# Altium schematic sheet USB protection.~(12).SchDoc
size A3; SheetNumber: 7; SheetTotal: 7
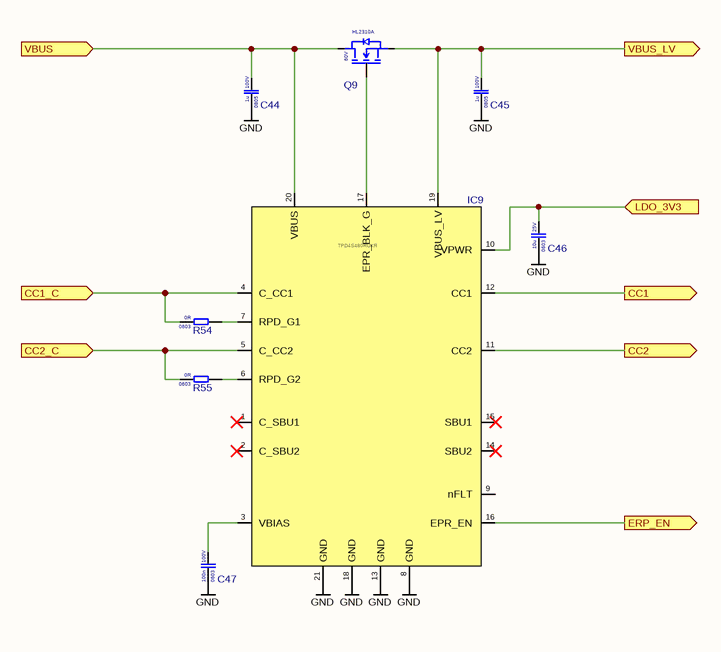
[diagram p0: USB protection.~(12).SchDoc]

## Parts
C44  Voltage Rating: 100V  Case Code (Imperial): 0805  Capacitance: 1u  [Cap_0805]  (hidden comment: CC0805KKX7R0BB105)
C45  Voltage Rating: 100V  Case Code (Imperial): 0805  Capacitance: 1u  [Cap_0805]  (hidden comment: CC0805KKX7R0BB105)
C46  Voltage Rating: 25V  Case Code (Imperial): 0603  Capacitance: 10u  [CAP 0603]  (hidden comment: CL10A106MA8NRNC)
C47  Voltage Rating: 100V  Case Code (Imperial): 0603  Capacitance: 100n  [CAP 0603]  (hidden comment: CC0603KRX7R0BB104)
IC9  TPD4S480RUKR  [WQFN (20)]
Q9  Voltage: 60V  [SOT-23 GSD]  (hidden comment: HL2310A)
R54  Resistance: 0R  Case Code (Imperial): 0603  [RES_0603]  (hidden comment: 0603WAF0000T5E)
R55  Resistance: 0R  Case Code (Imperial): 0603  [RES_0603]  (hidden comment: 0603WAF0000T5E)

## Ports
CC1 (out, see Arhitecture[3B], USB PD[3C]), CC1_C (in, see Arhitecture[2B]), CC2 (out, see Arhitecture[3B], USB PD[3C]), CC2_C (in, see Arhitecture[2B]), ERP_EN (out, see Arhitecture[3B], USB PD[5B]), LDO_3V3 (in, see Arhitecture[3B], USB PD[3C]), VBUS (in, see Arhitecture[2B], Power path switch[3B]), VBUS_LV (out, see Arhitecture[3B], USB PD[3B])

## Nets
GND: C44.1 C45.1 C46.1 C47.1 IC9.8(GND) IC9.13(GND) IC9.18(GND) IC9.21(GND)
CC1: IC9.12(CC1) ; port CC1
CC1_C: IC9.4(C_CC1) R54.1 ; port CC1_C
CC2: IC9.11(CC2) ; port CC2
CC2_C: IC9.5(C_CC2) R55.1 ; port CC2_C
ERP_EN: IC9.16(EPR_EN) ; port ERP_EN
LDO_3V3: C46.2 IC9.10(VPWR) ; port LDO_3V3
VBUS: C44.2 IC9.20(VBUS) Q9.D ; port VBUS
VBUS_LV: C45.2 IC9.19(VBUS_LV) Q9.S ; port VBUS_LV
NetC47_2: C47.2 IC9.3(VBIAS)
NetIC9_6: IC9.6(RPD_G2) R55.2
NetIC9_7: IC9.7(RPD_G1) R54.2
NetIC9_17: IC9.17(EPR_BLK_G) Q9.G

Not connected (* = marked no-connect by the designer): IC9 1(C_SBU1)* 2(C_SBU2)* 9(nFLT) 14(SBU2)* 15(SBU1)*

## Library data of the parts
C44 C45 = CC0805KKX7R0BB105: Cap 1uF 100V 0805 X7R; Manufacturer: Yageo
C46 = CL10A106MA8NRNC: Cap 10uF 25V 0603 X5R; Manufacturer: Samsung
C47 = CC0603KRX7R0BB104: Cap 100nF 100V 0603 X7R; Manufacturer: YAGEO
IC9 = TPD4S480RUKR: USB PD protection IC; Manufacturer: Texas Instruments
Q9 = HL2310A: nMOS 60V 3A SOT-23; Manufacturer: hongjiacheng
R54 R55 = 0603WAF0000T5E: Res 0R 0603 1% 100mW 75V; Manufacturer: UNI-ROYAL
